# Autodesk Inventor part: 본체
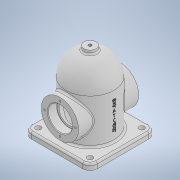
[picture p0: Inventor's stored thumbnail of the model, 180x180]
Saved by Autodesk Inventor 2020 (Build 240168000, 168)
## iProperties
Created: 2021-07
Part Number: 본체
Material: 일반
Document SubType Name: Modeling
Designer: Owner
Density: 1 g/cm^3
Appearance: 기본값
Author: Owner
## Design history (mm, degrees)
sketch "스케치2"
  geometry: C1 r 40 at (0, 0); 1 further point
  constraints: 1 centre point, 1 coincident
  dimensions: "d0" = 80 diameter of C1
extrude "돌출1" new body sketch "스케치2" distance "d1" = 124; taper "d2" = 0 deg
fillet "모깎기1" dims "d3" = 40
feature "쉘1" dims "d4" = 8
sketch "스케치3"
  geometry: L1 (55, 55)-(-55, 55); L2 (-55, 55)-(-55, -55); L3 (-55, -55)-(55, -55); L4 (55, -55)-(55, 55); L5 (55, 55)-(-55, -55); L6 (-55, 55)-(55, -55); C1 r 40 at (0, 0) reference; 1 further point
  constraints: 12 end point, 2 midpoint, 2 parallel, 1 horizontal, 1 perpendicular
  dimensions: "d5" = 110 distance of L3.end L2.end; "d6" = 110 distance of L2.end L1.end
extrude "돌출2" join sketch "스케치3" distance "d7" = 10; taper "d8" = 0 deg
fillet "모깎기2" dims "d9" = 12
sketch "스케치4"
  geometry: A1 r 12 centre (-43, -43) between (-55, -43) and (-43, -55) reference; 2 further points
  constraints: 1 coincident
hole "구멍1" sketch "스케치4" at (-43, -43) diameter "d10" = 9; stored, may be unused: countersink angle "d14" = 90 deg, drill point angle "d16" = 118 deg; dims "d11" = 6, "d12" = 4, "d13" = 2, "d15" = 8
node "작업 평면1"
sketch "스케치5"
  geometry: L1 (43, 0)-(-43, 0) reference; C1 r 31 at (0, 48); 2 further points
  constraints: 1 centre point, 1 midpoint, 1 vertical alignment
  dimensions: "d18" = 62 diameter of C1; "d19" = 48 distance from line of L1 C1.centre
extrude "돌출3" join sketch "스케치5" stored distance "d20" = 10; taper "d21" = 0 deg
sketch "스케치6"
  geometry: C1 r 31 at (0, 0) reference; 2 further points
  constraints: 1 coincident
hole "구멍2" sketch "스케치6" at (0, 0) diameter "d22" = 33; stored, may be unused: countersink angle "d26" = 90 deg, drill point angle "d28" = 118 deg; dims "d23" = 6, "d24" = 40, "d25" = 15, "d27" = 50
node "작업 평면2"
sketch "스케치7"
  geometry: C1 r 10 at (0, 0); 1 further point
  constraints: 1 centre point, 1 coincident
  dimensions: "d30" = 20 diameter of C1
extrude "돌출4" join sketch "스케치7" stored distance "d31" = 10; taper "d32" = 0 deg
sketch "스케치8"
  geometry: C1 r 10 at (0, 0) reference; 2 further points
  constraints: 1 coincident
hole "구멍3" sketch "스케치8" at (0, 0) diameter "d33" = 5.1881; stored, may be unused: countersink angle "d37" = 90 deg, drill point angle "d39" = 118 deg; dims "d34" = 12, "d35" = 40, "d36" = 15, "d38" = 16
sketch "스케치9"
  geometry: C1 r 31 at (0, 0) reference; C2 r 20 at (0, 0) reference; 3 further points
  constraints: 1 coincident, 1 vertical alignment
  dimensions: "d40" = 25.5 distance of point (0, 0) point (0, 25.5)
hole "구멍4" sketch "스케치9" at (0, 0), (0, 25.5) diameter "d41" = 3.242; stored, may be unused: countersink angle "d45" = 90 deg, drill point angle "d47" = 118 deg; dims "d42" = 8, "d43" = 40, "d44" = 15, "d46" = 10
node "작업 평면3"
sketch "스케치10"
  geometry: L1 (0, -43)-(0, 43) reference; 3 further points
  constraints: 1 horizontal alignment, 1 midpoint, 1 other
  dimensions: "d51" = 48 distance from line of L1 point (48, 0)
feature "엠보싱1" sketch "스케치10" dims "d9" = 12, "d52" = 0.5, "d53" = 0
fillet "모깎기3" dims "d54" = 3
chamfer "모따기1" distance "d55" = 1; stored, may be unused: second distance "d56" = 2, angle "d57" = 45 deg
fillet "모깎기4" dims "d58" = 0.3
node "솔리드1"
mirror "미러1"
mirror "미러2"
mirror "미러3"
pattern_circular "원형 패턴1" dims angle "d49" = 360 deg
mirror "미러4"
feature "A9D066F2-1C7D-4E18-AEED-F7BC21143FA4" dims "d10" = 9, "d11" = 6, "d12" = 4, "d13" = 2, "d14" = 90 deg, "d15" = 8, "d16" = 118 deg
other parameters: "d29" = 129
